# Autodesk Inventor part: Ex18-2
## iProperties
Author: Elise Moss
Revision Number: A
Created: 2001-09
Part Number: Ex18-2
Material: Default
Description: SLIDING JAW
Document SubType Name: Modeling
Designer: Elise Moss
Control State: 0
Master: False
Checked Out: False
PropertySet Name: Design Tracking Control
Length Units: 11272
Angle Units: 11279
Time Units: 11290
Mass Units: 11286
Shininess: 3
Angle Display Precision: 2
Document Length Units: 11272
Document Angle Units: 11286
Document Time Units: 11279
Document Mass Units: 11290
Document Length Units Precision: 3
Document Angle Units Precision: 0
Compacted: False
PropertySet Name: _Private Model Information
Density: 1.0
Volumn: 50.225593889828225
Area: 104.15334877664131
PropertySet Name: Model Information
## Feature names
1. Extrusion1
2. Extrusion2
3. Extrusion3
4. Extrusion4
5. Hole1
6. Hole2
7. Hole3
